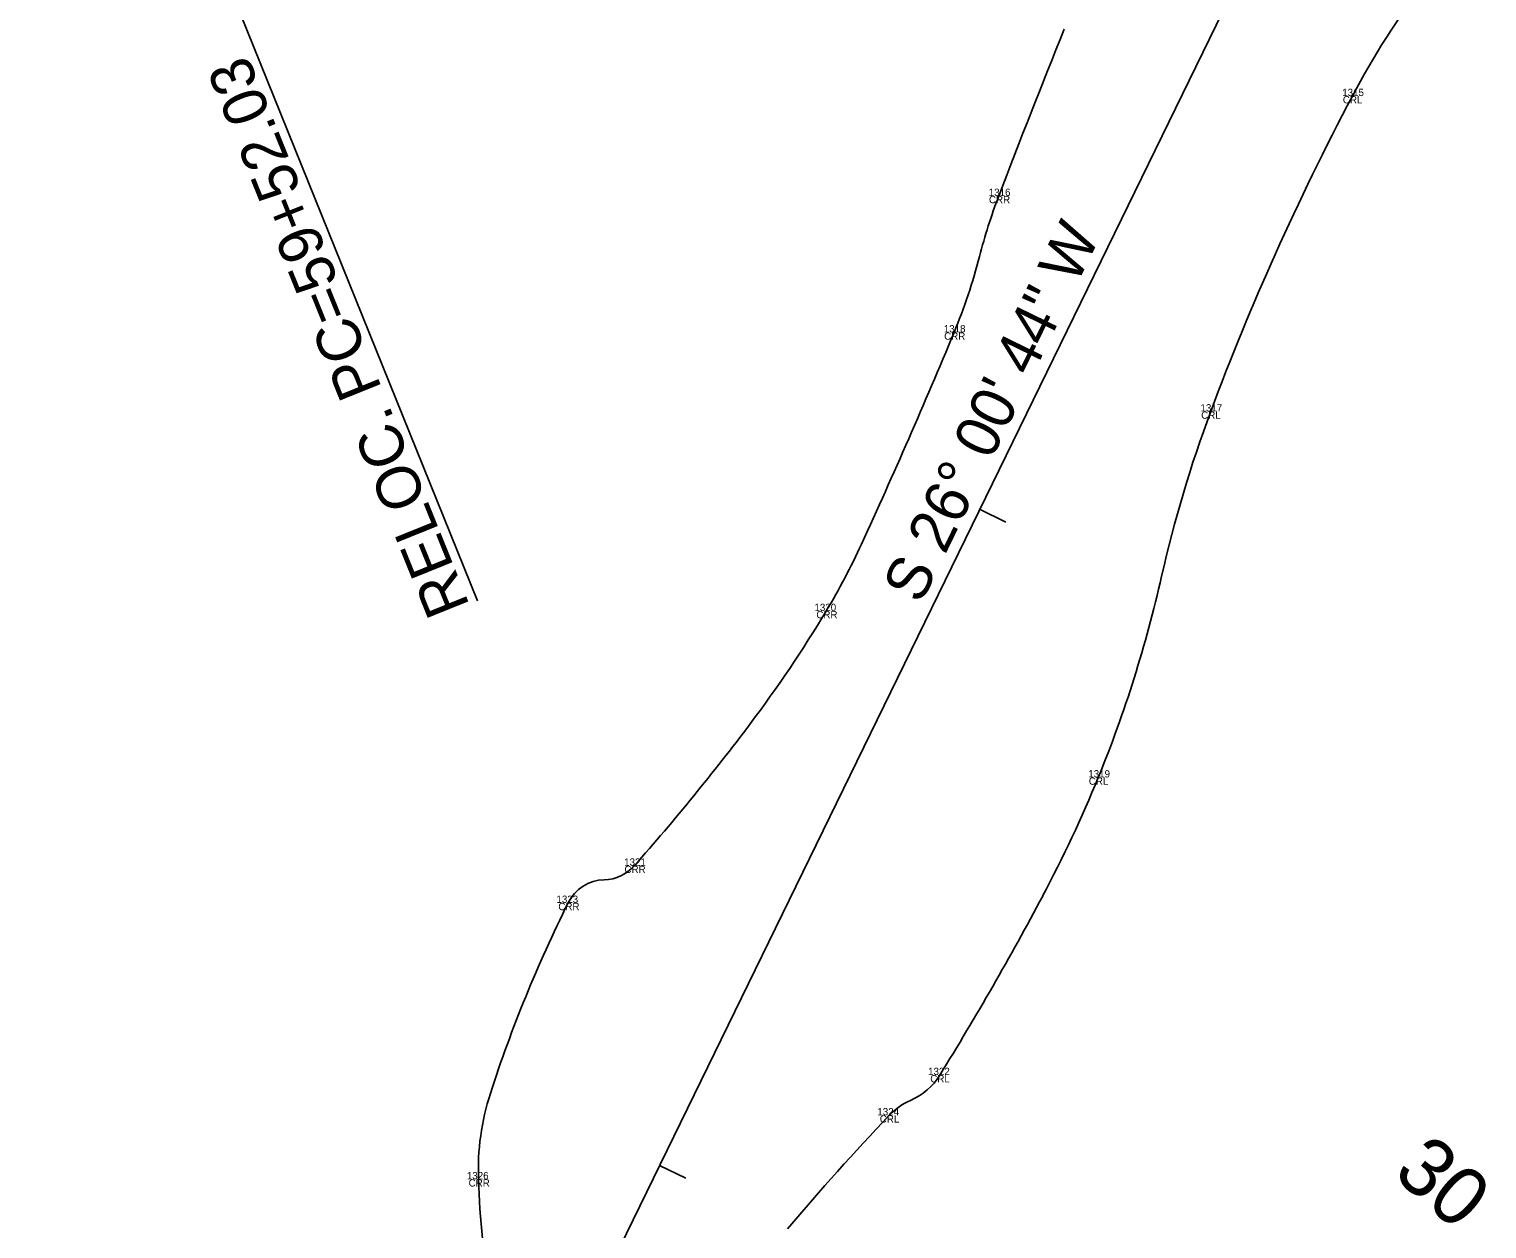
# Model space of a CAD drawing. Extents: x 1965498 to 1971309, y 1116335 to 1119906.
# Drawn here: x 1967653.5 to 1967853.2, y 1117566.6 to 1117730.9 of the extents above; entities that cross this region are included whole.
import ezdxf

# ---------------------------------------------------------------- set-up
doc = ezdxf.new("R2010")
doc.units = 0
for name, color, linetype in [('Level 1', 7, 'Continuous'), ('Level 10', 7, 'Continuous'), ('Level 12', 7, 'Continuous'), ('Level 21', 7, 'Continuous'), ('Level 39', 7, 'Continuous'), ('Level 50', 7, 'Continuous'), ('Level 60', 7, 'Continuous'), ('Level 61', 7, 'Continuous')]:
    doc.layers.add(name, color=color, linetype=linetype)

msp = doc.modelspace()

# ---------------------------------------------------------------- linework, layer by layer
at = {"layer": 'Level 1'}
for p, q in [((1967849.81, 1117800.6), (1967729.31, 1117553.65)), ((1967783.7, 1117665.12), (1967787.29, 1117663.36)), ((1967739.84, 1117575.25), (1967743.44, 1117573.49))]:
    msp.add_line(p, q, dxfattribs=at)
at = {"layer": 'Level 10'}
for centre, radius, start, end in [((1967934.8, 1117668.92), 113.11, 142.7528, 152.1702), ((1969020.63, 1117236.93), 1321.15, 158.04475, 159.10929), ((1968170.7, 1117544.39), 379.86, 152.1702, 155.7997), ((1967859.29, 1117680.19), 78.1, 159.1093, 165.4847), ((1967708.08, 1117719.34), 78.1, 337.4169, 345.4847), ((1968149.99, 1117553.7), 357.15, 155.7997, 159.5429), ((1966969.24, 1118026.63), 878.3, 335.3531, 337.41691), ((1967979.14, 1117617.43), 174.8, 159.5429, 167.2693), ((1967681.76, 1117699.71), 94.35, 329.0536, 335.3531), ((1967638.13, 1117694.47), 174.8, 337.7883, 347.2693), ((1967611.44, 1117741.87), 176.34, 323.0003, 329.0536), ((1967496.28, 1117828.65), 320.54, 318.5113, 323.0003), ((1967636.61, 1117695.09), 176.44, 331.9552, 337.7883), ((1967732.11, 1117620.08), 5.71, 271.6263, 318.5113), ((1967732.44, 1117608.67), 5.71, 91.6263, 153.5659), ((1967406.45, 1117817.7), 437.23, 328.2506, 331.9552), ((1967898.57, 1117526.08), 191.24, 153.5659, 162.0204), ((1967770.68, 1117592.31), 8.9, 293.5297, 328.2506), ((1967748.92, 1117574.64), 33.9, 162.0204, 182.1852), ((1967777.79, 1117576), 8.9, 113.5297, 136.5792), ((1968053.04, 1117315.51), 387.87, 136.5792, 139.6643), ((1967857.88, 1117578.8), 142.95, 182.1852, 195.2389)]:
    msp.add_arc(centre, radius, start, end, dxfattribs=at)
at = {"layer": 'Level 12'}
msp.add_line((1967849.81, 1117800.6), (1967729.31, 1117553.65), dxfattribs=at)
at = {"layer": 'Level 39'}
msp.add_line((1967653.48, 1117804.69), (1967714.92, 1117652.58), dxfattribs=at)
at = {"layer": 'Level 50'}
for centre in [(1967834.78, 1117721.72), (1967786.33, 1117708.04), (1967780.19, 1117689.35), (1967815.36, 1117678.52), (1967762.68, 1117651.19), (1967799.96, 1117628.39), (1967736.39, 1117616.3), (1967727.33, 1117611.21), (1967778.25, 1117587.63), (1967771.33, 1117582.11), (1967715.04, 1117573.35)]:
    msp.add_circle(centre, 0.001, dxfattribs=at)

# ---------------------------------------------------------------- texts
at = {"layer": 'Level 21'}
for s, height, rotation, p in [('S 26%%d 00\' 44" W', 6, 63.9877, (1967775.62, 1117651.98)), ('30', 8, 318.9993, (1967840.14, 1117573.91))]:
    msp.add_text(s, height=height, rotation=rotation, dxfattribs=at).set_placement(p)
at = {"layer": 'Level 39'}
msp.add_text('RELOC. PC=59+52.03', height=6, rotation=111.9958, dxfattribs=at).set_placement((1967713.89, 1117651.89))
at = {"layer": 'Level 60'}
for s, p in [('CRL', (1967833.47, 1117720.72)), ('CRR', (1967784.98, 1117707.04)), ('CRR', (1967778.84, 1117688.35)), ('CRL', (1967814.06, 1117677.52)), ('CRR', (1967761.33, 1117650.19)), ('CRL', (1967798.66, 1117627.39)), ('CRR', (1967735.04, 1117615.3)), ('CRR', (1967725.98, 1117610.21)), ('CRL', (1967776.94, 1117586.63)), ('CRL', (1967770.02, 1117581.11)), ('CRR', (1967713.69, 1117572.35))]:
    msp.add_text(s, height=1, dxfattribs=at).set_placement(p)
at = {"layer": 'Level 61'}
for s, p in [('1315', (1967833.38, 1117721.72)), ('1316', (1967784.95, 1117708.04)), ('1318', (1967778.79, 1117689.35)), ('1317', (1967813.96, 1117678.52)), ('1320', (1967761.07, 1117651.19)), ('1319', (1967798.59, 1117628.39)), ('1321', (1967735, 1117616.3)), ('1323', (1967725.72, 1117611.21)), ('1322', (1967776.64, 1117587.63)), ('1324', (1967769.69, 1117582.11)), ('1326', (1967713.45, 1117573.35))]:
    msp.add_text(s, height=1, dxfattribs=at).set_placement(p)

doc.saveas('drawing.dxf')
